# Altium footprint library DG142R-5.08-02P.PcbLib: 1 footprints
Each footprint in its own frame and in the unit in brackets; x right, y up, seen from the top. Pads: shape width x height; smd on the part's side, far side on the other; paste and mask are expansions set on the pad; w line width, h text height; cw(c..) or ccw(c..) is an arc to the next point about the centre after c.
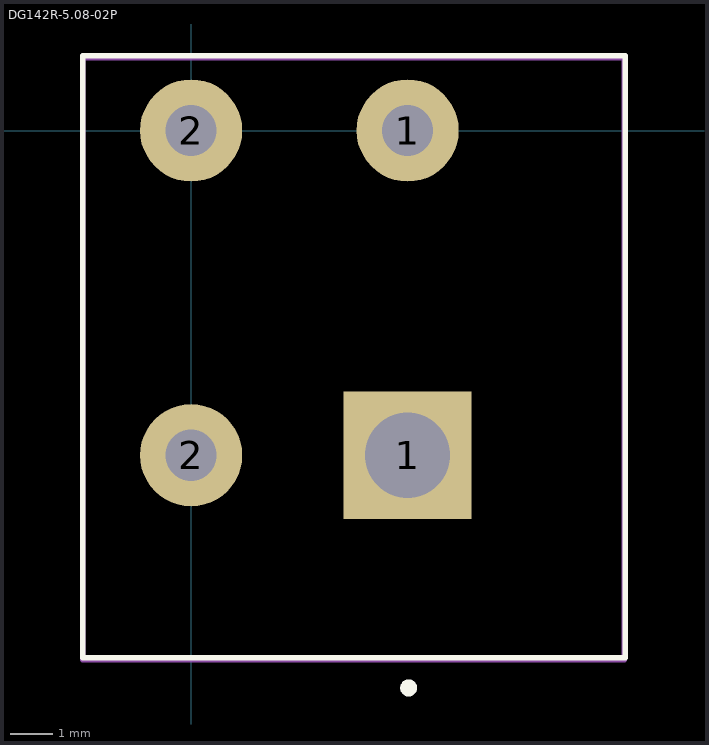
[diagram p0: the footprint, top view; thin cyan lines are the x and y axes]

## DG142R-5.08-02P [mm]
pads (4):
  rect 3x3 hole 2: 1(5.08,-7.62)
  round 2.4 hole 1.2: 1(5.08,0) 2(0,-7.62) 2(0,0)
Top Overlay:
  circle w0.2: c5.105,-13.081 r0.1
  lines w0.127: -2.54,-12.37 -2.54,1.753 10.185,1.753 10.185,-12.37 -2.54,-12.37
Mechanical 13:
  lines w0.127: -2.54,-12.421 10.16,-12.421 10.16,1.702 -2.54,1.702 -2.54,-12.421
3D body "DG142R-5.08-02P.stp": height 13.43, standoff -3.47, extent -2.29,-12.407 10.11,1.693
